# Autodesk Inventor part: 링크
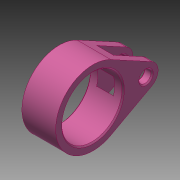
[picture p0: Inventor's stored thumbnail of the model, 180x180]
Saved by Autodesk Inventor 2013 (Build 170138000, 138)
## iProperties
Created: 2016-02
Part Number: 링크
Material: 강철, 연강
Document SubType Name: Modeling
Designer: test
Density: 1 g/cm^3
Author: test
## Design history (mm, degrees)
sketch "스케치1"
  geometry: L1 (24.386, 4.394)-(7.398, 13.621); L2 (24.386, -4.394)-(7.398, -13.621); A1 r 15.5 centre (0, 0) between (7.398, 13.621) and (7.398, -13.621); A2 r 5 centre (22, 0) between (24.386, -4.394) and (24.386, 4.394); 1 further point
  constraints: 4 end point, 4 point on circle, 4 tangent, 2 centre point, 1 coincident, 1 horizontal alignment
  dimensions: "d0" = 22 distance of point (0, 0) A2.centre; "d1" = 15.5 radius of A1; "d2" = 5 radius of A2
extrude "돌출1" new body sketch "스케치1" stored distance "d3" = 14; taper "d4" = 0 deg
sketch "스케치2"
  geometry: C1 r 12.5 at (0, 0); 1 further point
  constraints: 1 centre point, 1 coincident
  dimensions: "d5" = 25 diameter of C1
extrude "돌출2" cut sketch "스케치2" stored distance "d6" = 14; taper "d7" = 0 deg
sketch "스케치3"
  geometry: C1 r 2.5 at (22, 0); A1 r 5 centre (22, 0) between (24.386, -4.394) and (24.386, 4.394) reference; 1 further point
  constraints: 1 centre point, 1 coincident
  dimensions: "d8" = 5 diameter of C1
extrude "돌출3" cut sketch "스케치3" stored distance "d9" = 14; taper "d10" = 0 deg
sketch "스케치4"
  geometry: L1 (24.386, -4.394)-(7.398, -13.621) reference; L2 (7.398, 13.621)-(24.386, 4.394) reference; L3 (15, 9.492)-(15, -9.492); C1 r 2.5 at (22, 0) reference; C2 r 12.5 at (0, 0) reference; A1 r 15.5 centre (0, 0) between (7.398, 13.621) and (7.398, -13.621) reference; A2 r 5 centre (22, 0) between (24.386, -4.394) and (24.386, 4.394) reference; 1 further point
  constraints: 2 end point, 2 point on line, 1 vertical
  dimensions: "d11" = 15 distance from line of L3 point (0, 0)
extrude "돌출4" cut sketch "스케치4" stored distance "d12" = 7; taper "d13" = 0 deg
chamfer "모따기1" distance "d14" = 0.5; stored, may be unused: second distance "d15" = 2, angle "d16" = 45 deg
node "솔리드1"
node "절단 모서리 투영1"
